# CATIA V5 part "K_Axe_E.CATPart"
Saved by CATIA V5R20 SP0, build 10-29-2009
Part number: Axe_E
Bounding box of the stored display mesh (mm): x -6 to 6, y -6 to 6, z 0 to 45.828
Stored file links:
  G:\Khaled_CFAO_2011\ST2M\ST2M_GR2\echouteau\Khaled\CAD_ThinkMotion\K_Axe_E.CATPart
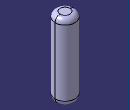
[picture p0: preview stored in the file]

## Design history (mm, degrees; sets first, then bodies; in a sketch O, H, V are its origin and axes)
AxisSystem1: origin (0, 0, 0), X (1, 0, 0), Y (0, 1, 0), Z (0, 0, 1)
Body1 (main body)
  Sketch1 on XY plane of AxisSystem1, origin (0, 0, 0), H (1, 0, 0), V (0, 1, 0)
    circle A1 centre (0, 0) radius 6
    radius A1 = 6
  Pad1: profile Sketch1, direction (0, 0, 1), length 45.828
  Fillet1: radius 3, on end face of Pad1
  Fillet2: radius 3, on edge [start face of Pad1 | face of Pad1 from Sketch1.A1]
